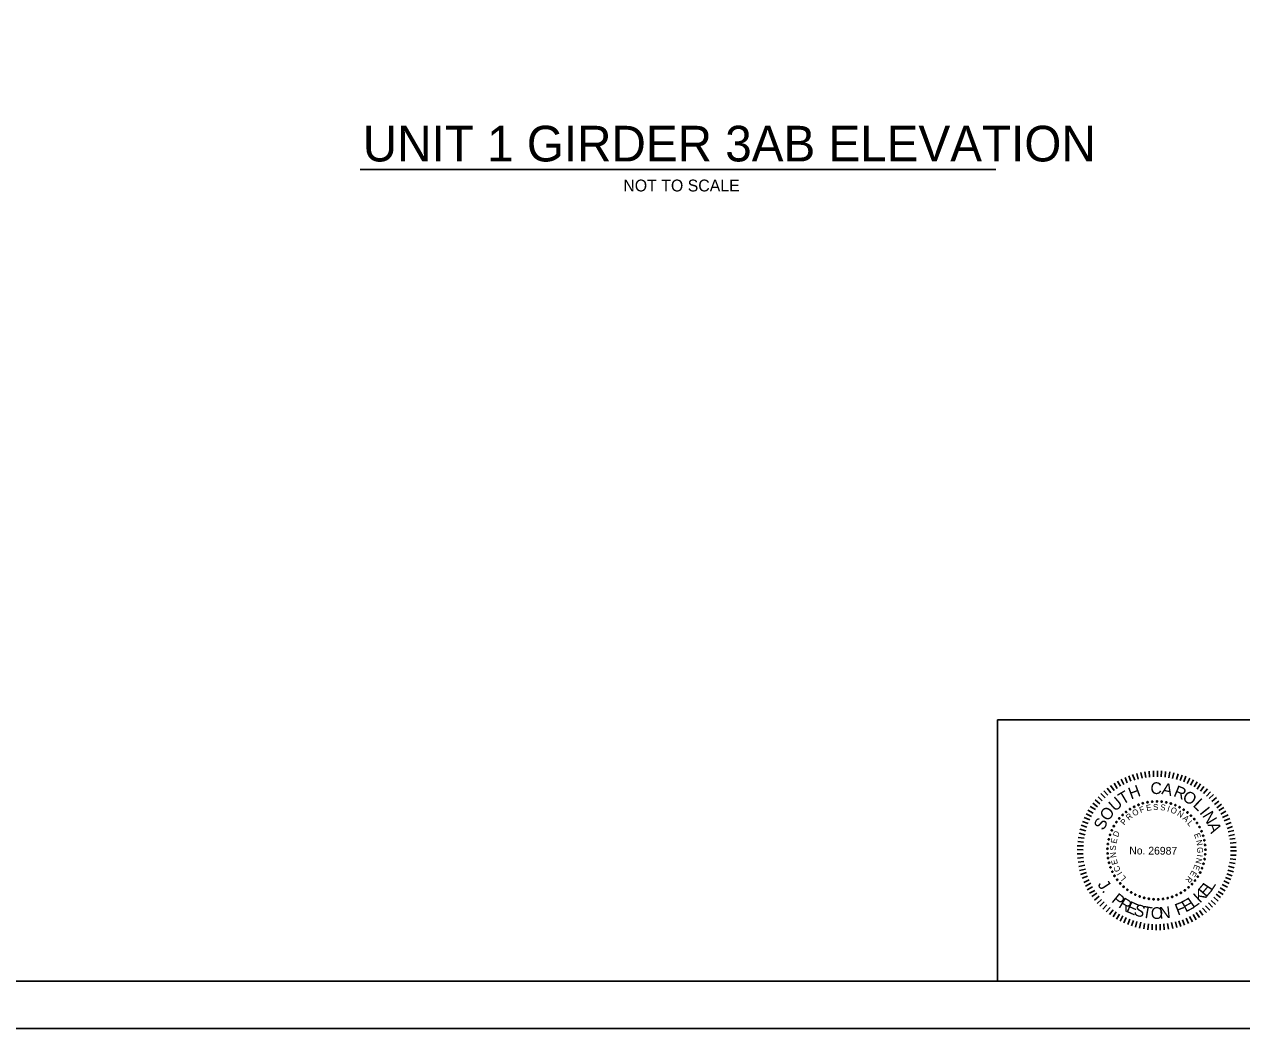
# Model space of a CAD drawing. Extents: x -383 to 7, y -330 to -94.
# Drawn here: x -255.6 to -204.4, y -187.5 to -145.2 of the extents above; entities that cross this region are included whole.
import ezdxf

# ---------------------------------------------------------------- set-up
doc = ezdxf.new("R2010")
doc.units = 0
for name, color, linetype in [('BR_BORDER LINES', 7, 'Continuous'), ('BR_TEXT', 7, 'Continuous'), ('Level 31', 7, 'Continuous')]:
    doc.layers.add(name, color=color, linetype=linetype)

msp = doc.modelspace()

# ---------------------------------------------------------------- linework, layer by layer
at = {"layer": 'BR_BORDER LINES'}
for p, q in [((-214.64, -174.489), (-193.18, -174.489)), ((-214.64, -185.489), (-214.64, -174.489)), ((-297.843, -185.489), (-163.178, -185.489))]:
    msp.add_line(p, q, dxfattribs=at)
at = {"layer": 'BR_TEXT'}
for p, q in [((-241.481, -151.32), (-214.712, -151.32)), ((-209.02, -177.076), (-209.103, -176.842)), ((-208.861, -177.026), (-208.949, -176.795)), ((-208.717, -176.986), (-208.77, -176.742)), ((-208.552, -176.946), (-208.608, -176.709)), ((-208.394, -176.917), (-208.429, -176.673)), ((-208.236, -176.901), (-208.251, -176.657)), ((-208.077, -176.892), (-208.075, -176.634)), ((-207.909, -176.883), (-207.907, -176.636)), ((-207.741, -176.895), (-207.732, -176.637)), ((-207.58, -176.906), (-207.561, -176.663)), ((-207.426, -176.925), (-207.382, -176.681)), ((-207.265, -176.957), (-207.208, -176.721)), ((-207.1, -176.999), (-207.036, -176.756)), ((-206.953, -177.042), (-206.865, -176.813)), ((-206.795, -177.095), (-206.708, -176.862)), ((-209.861, -177.564), (-210.021, -177.363)), ((-209.726, -177.462), (-209.883, -177.258)), ((-209.602, -177.377), (-209.724, -177.16)), ((-209.461, -177.282), (-209.582, -177.065)), ((-209.323, -177.211), (-209.427, -176.987)), ((-209.175, -177.144), (-209.269, -176.92)), ((-206.652, -177.165), (-206.54, -176.942)), ((-206.508, -177.234), (-206.383, -177.012)), ((-206.358, -177.308), (-206.229, -177.093)), ((-206.225, -177.405), (-206.089, -177.19)), ((-206.091, -177.492), (-205.946, -177.291)), ((-205.962, -177.596), (-205.799, -177.398)), ((-210.328, -178.02), (-210.526, -177.864)), ((-210.228, -177.894), (-210.402, -177.724)), ((-210.11, -177.771), (-210.287, -177.594)), ((-209.993, -177.662), (-210.159, -177.482)), ((-205.836, -177.696), (-205.663, -177.519)), ((-205.723, -177.807), (-205.55, -177.634)), ((-205.611, -177.932), (-205.421, -177.765)), ((-205.502, -178.06), (-205.316, -177.907)), ((-210.686, -178.552), (-210.912, -178.441)), ((-210.617, -178.416), (-210.832, -178.287)), ((-210.519, -178.269), (-210.735, -178.137)), ((-210.432, -178.153), (-210.63, -177.993)), ((-205.407, -178.194), (-205.21, -178.038)), ((-205.319, -178.312), (-205.109, -178.183)), ((-205.231, -178.46), (-205.017, -178.335)), ((-210.876, -179.014), (-211.122, -178.923)), ((-210.826, -178.853), (-211.059, -178.766)), ((-210.756, -178.699), (-210.985, -178.598)), ((-205.16, -178.598), (-204.929, -178.49)), ((-205.089, -178.746), (-204.862, -178.648)), ((-205.022, -178.901), (-204.795, -178.817)), ((-210.996, -179.47), (-211.24, -179.437)), ((-210.954, -179.326), (-211.204, -179.262)), ((-210.925, -179.158), (-211.168, -179.098)), ((-204.968, -179.063), (-204.738, -178.976)), ((-204.928, -179.207), (-204.688, -179.151)), ((-204.895, -179.376), (-204.654, -179.316)), ((-211.034, -179.957), (-211.285, -179.955)), ((-211.026, -179.792), (-211.284, -179.79)), ((-211.015, -179.634), (-211.261, -179.605)), ((-204.862, -179.52), (-204.625, -179.491)), ((-204.836, -179.685), (-204.592, -179.66)), ((-204.831, -179.843), (-204.59, -179.845)), ((-211.029, -180.129), (-211.286, -180.133)), ((-211.02, -180.283), (-211.267, -180.312)), ((-211.004, -180.448), (-211.248, -180.484)), ((-204.841, -180.334), (-204.598, -180.367)), ((-204.833, -180.18), (-204.593, -180.189)), ((-204.822, -180.008), (-204.578, -180.01)), ((-210.964, -180.606), (-211.215, -180.659)), ((-210.938, -180.775), (-211.182, -180.831)), ((-210.891, -180.923), (-211.139, -181.006)), ((-204.984, -180.971), (-204.755, -181.059)), ((-204.942, -180.824), (-204.702, -180.885)), ((-204.906, -180.656), (-204.666, -180.713)), ((-204.87, -180.499), (-204.634, -180.538)), ((-210.845, -181.077), (-211.079, -181.161)), ((-210.777, -181.226), (-211.008, -181.334)), ((-210.71, -181.37), (-210.937, -181.489)), ((-205.183, -181.416), (-204.954, -181.538)), ((-205.11, -181.272), (-204.884, -181.384)), ((-205.04, -181.125), (-204.814, -181.213)), ((-210.642, -181.519), (-210.859, -181.644)), ((-210.547, -181.667), (-210.765, -181.792)), ((-210.462, -181.784), (-210.663, -181.93)), ((-210.361, -181.919), (-210.561, -182.075)), ((-205.535, -181.959), (-205.351, -182.118)), ((-205.437, -181.826), (-205.243, -181.975)), ((-205.347, -181.71), (-205.139, -181.839)), ((-205.257, -181.563), (-205.045, -181.692)), ((-210.262, -182.054), (-210.439, -182.217)), ((-210.146, -182.158), (-210.326, -182.338)), ((-210.031, -182.279), (-210.2, -182.463)), ((-209.901, -182.383), (-210.064, -182.57)), ((-209.768, -182.487), (-209.928, -182.678)), ((-206.133, -182.517), (-205.99, -182.71)), ((-206.002, -182.415), (-205.842, -182.605)), ((-205.874, -182.313), (-205.704, -182.5)), ((-205.76, -182.194), (-205.589, -182.377)), ((-205.645, -182.092), (-205.458, -182.258)), ((-209.645, -182.574), (-209.77, -182.782)), ((-209.505, -182.664), (-209.63, -182.879)), ((-209.368, -182.744), (-209.477, -182.967)), ((-209.221, -182.814), (-209.319, -183.037)), ((-209.068, -182.884), (-209.155, -183.11)), ((-208.91, -182.933), (-209.001, -183.166)), ((-208.766, -182.983), (-208.823, -183.219)), ((-208.602, -183.011), (-208.662, -183.258)), ((-207.315, -183.022), (-207.262, -183.27)), ((-207.15, -182.996), (-207.09, -183.233)), ((-207.002, -182.949), (-206.918, -183.183)), ((-206.843, -182.902), (-206.759, -183.13)), ((-206.699, -182.835), (-206.591, -183.059)), ((-206.554, -182.768), (-206.432, -182.992)), ((-206.402, -182.69), (-206.277, -182.907)), ((-206.268, -182.602), (-206.135, -182.812)), ((-208.444, -183.057), (-208.484, -183.29)), ((-208.287, -183.076), (-208.306, -183.323)), ((-208.129, -183.087), (-208.131, -183.335)), ((-207.961, -183.099), (-207.963, -183.343)), ((-207.792, -183.09), (-207.787, -183.338)), ((-207.631, -183.081), (-207.616, -183.329)), ((-207.476, -183.065), (-207.437, -183.299))]:
    msp.add_line(p, q, dxfattribs=at)
for centre, start, end in [((-208.126, -177.93), 5.0653, 185.0653), ((-208.126, -177.93), 185.0653, 5.0653), ((-207.926, -177.923), 359.5268, 179.5268), ((-207.926, -177.923), 179.5268, 359.5268), ((-207.727, -177.934), 353.9884, 173.9884), ((-209.223, -178.364), 38.2961, 218.2961), ((-209.223, -178.364), 218.2961, 38.2961), ((-209.06, -178.248), 32.7576, 212.7576), ((-209.06, -178.248), 212.7576, 32.7576), ((-208.887, -178.149), 27.2191, 207.2191), ((-208.887, -178.149), 207.2191, 27.2191), ((-208.706, -178.067), 21.6807, 201.6807), ((-208.706, -178.067), 201.6807, 21.6807), ((-208.517, -178.003), 16.1422, 196.1422), ((-208.517, -178.003), 196.1422, 16.1422), ((-208.323, -177.957), 10.6038, 190.6038), ((-208.323, -177.957), 190.6038, 10.6038), ((-207.727, -177.934), 173.9884, 353.9884), ((-207.531, -177.965), 168.4499, 348.4499), ((-207.531, -177.965), 348.4499, 168.4499), ((-207.338, -178.015), 162.9114, 342.9114), ((-207.338, -178.015), 342.9114, 162.9114), ((-207.15, -178.083), 157.373, 337.373), ((-207.15, -178.083), 337.373, 157.373), ((-206.97, -178.169), 151.8345, 331.8345), ((-206.97, -178.169), 331.8345, 151.8345), ((-206.8, -178.272), 146.2961, 326.2961), ((-206.8, -178.272), 326.2961, 146.2961), ((-206.639, -178.39), 140.7576, 320.7576), ((-206.639, -178.39), 320.7576, 140.7576), ((-209.74, -178.964), 60.4499, 240.4499), ((-209.74, -178.964), 240.4499, 60.4499), ((-209.633, -178.796), 54.9114, 234.9114), ((-209.633, -178.796), 234.9114, 54.9114), ((-209.511, -178.639), 49.373, 229.373), ((-209.511, -178.639), 229.373, 49.373), ((-209.373, -178.495), 43.8345, 223.8345), ((-209.373, -178.495), 223.8345, 43.8345), ((-206.492, -178.524), 135.2191, 315.2191), ((-206.492, -178.524), 315.2191, 135.2191), ((-206.357, -178.671), 129.6807, 309.6807), ((-206.357, -178.671), 309.6807, 129.6807), ((-206.238, -178.831), 124.1422, 304.1422), ((-206.238, -178.831), 304.1422, 124.1422), ((-209.903, -179.328), 71.5268, 251.5268), ((-209.903, -179.328), 251.5268, 71.5268), ((-209.83, -179.142), 65.9884, 245.9884), ((-209.83, -179.142), 245.9884, 65.9884), ((-206.135, -179.001), 118.6038, 298.6038), ((-206.135, -179.001), 298.6038, 118.6038), ((-206.048, -179.181), 113.0653, 293.0653), ((-206.048, -179.181), 293.0653, 113.0653), ((-205.979, -179.368), 107.5268, 287.5268), ((-205.979, -179.368), 287.5268, 107.5268), ((-210.009, -179.914), 88.1422, 268.1422), ((-209.993, -179.716), 82.6038, 262.6038), ((-210.009, -179.914), 268.1422, 88.1422), ((-209.993, -179.716), 262.6038, 82.6038), ((-209.957, -179.52), 77.0653, 257.0653), ((-209.957, -179.52), 257.0653, 77.0653), ((-205.929, -179.561), 101.9884, 281.9884), ((-205.929, -179.561), 281.9884, 101.9884), ((-205.897, -179.758), 96.4499, 276.4499), ((-205.885, -179.957), 90.9114, 270.9114), ((-205.897, -179.758), 276.4499, 96.4499), ((-205.885, -179.957), 270.9114, 90.9114), ((-210.006, -180.114), 93.6807, 273.6807), ((-209.984, -180.312), 99.2191, 279.2191), ((-210.006, -180.114), 273.6807, 93.6807), ((-209.984, -180.312), 279.2191, 99.2191), ((-209.943, -180.507), 104.7576, 284.7576), ((-209.943, -180.507), 284.7576, 104.7576), ((-205.918, -180.353), 79.8345, 259.8345), ((-205.918, -180.353), 259.8345, 79.8345), ((-205.892, -180.156), 85.373, 265.373), ((-205.892, -180.156), 265.373, 85.373), ((-209.884, -180.697), 110.2961, 290.2961), ((-209.884, -180.697), 290.2961, 110.2961), ((-209.806, -180.881), 115.8345, 295.8345), ((-209.806, -180.881), 295.8345, 115.8345), ((-206.108, -180.918), 63.2191, 243.2191), ((-206.108, -180.918), 243.2191, 63.2191), ((-206.026, -180.737), 68.7576, 248.7576), ((-206.026, -180.737), 248.7576, 68.7576), ((-205.963, -180.548), 74.2961, 254.2961), ((-205.963, -180.548), 254.2961, 74.2961), ((-209.711, -181.056), 121.373, 301.373), ((-209.711, -181.056), 301.373, 121.373), ((-209.599, -181.221), 126.9114, 306.9114), ((-209.599, -181.221), 306.9114, 126.9114), ((-209.472, -181.375), 132.4499, 312.4499), ((-209.472, -181.375), 312.4499, 132.4499), ((-209.331, -181.515), 137.9884, 317.9884), ((-209.331, -181.515), 317.9884, 137.9884), ((-206.596, -181.543), 41.0653, 221.0653), ((-206.452, -181.406), 46.6038, 226.6038), ((-206.452, -181.406), 226.6038, 46.6038), ((-206.321, -181.255), 52.1422, 232.1422), ((-206.321, -181.255), 232.1422, 52.1422), ((-206.207, -181.092), 57.6807, 237.6807), ((-206.207, -181.092), 237.6807, 57.6807), ((-209.177, -181.642), 143.5268, 323.5268), ((-209.177, -181.642), 323.5268, 143.5268), ((-209.011, -181.753), 149.0653, 329.0653), ((-209.011, -181.753), 329.0653, 149.0653), ((-208.836, -181.847), 154.6038, 334.6038), ((-208.836, -181.847), 334.6038, 154.6038), ((-208.652, -181.924), 160.1422, 340.1422), ((-208.652, -181.924), 340.1422, 160.1422), ((-208.462, -181.983), 165.6807, 345.6807), ((-208.462, -181.983), 345.6807, 165.6807), ((-208.267, -182.023), 171.2191, 351.2191), ((-208.267, -182.023), 351.2191, 171.2191), ((-208.068, -182.045), 356.7576, 176.7576), ((-207.869, -182.047), 2.2961, 182.2961), ((-207.67, -182.029), 7.8345, 187.8345), ((-207.67, -182.029), 187.8345, 7.8345), ((-207.474, -181.993), 13.373, 193.373), ((-207.474, -181.993), 193.373, 13.373), ((-207.283, -181.938), 18.9114, 198.9114), ((-207.283, -181.938), 198.9114, 18.9114), ((-207.098, -181.865), 24.4499, 204.4499), ((-207.098, -181.865), 204.4499, 24.4499), ((-206.92, -181.774), 29.9884, 209.9884), ((-206.92, -181.774), 209.9884, 29.9884), ((-206.752, -181.667), 35.5268, 215.5268), ((-206.752, -181.667), 215.5268, 35.5268), ((-206.596, -181.543), 221.0653, 41.0653), ((-208.068, -182.045), 176.7576, 356.7576), ((-207.869, -182.047), 182.2961, 2.2961)]:
    msp.add_arc(centre, 0.028, start, end, dxfattribs=at)
at = {"layer": 'Level 31'}
msp.add_lwpolyline([(-305.176, -187.489), (-161.176, -187.489), (-161.176, -99.489), (-305.176, -99.489)], close=True, dxfattribs=at)

# ---------------------------------------------------------------- texts
at = {"layer": 'BR_TEXT'}
for s, height, p in [('UNIT 1 GIRDER 3AB ELEVATION', 1.5, (-241.378, -150.983)), ('NOT TO SCALE', 0.5, (-230.403, -152.247))]:
    msp.add_text(s, height=height, dxfattribs=at).set_placement(p)
for s, height, rotation, p in [('H', 0.496, 20.3637, (-209.018, -177.846)), ('C', 0.496, 359.5482, (-208.2, -177.612)), ('A', 0.496, 348.1981, (-207.755, -177.609)), ('R', 0.496, 337.4344, (-207.262, -177.689)), ('U', 0.496, 40.8022, (-209.694, -178.375)), ('T', 0.496, 30.4992, (-209.37, -178.076)), ('O', 0.496, 326.5869, (-206.893, -177.836)), ('L', 0.496, 315.9488, (-206.442, -178.107)), ('O', 0.496, 52.0267, (-209.993, -178.79)), ('R', 0.249, 40.3949, (-209.107, -178.737)), ('O', 0.249, 30.8477, (-208.882, -178.561)), ('F', 0.249, 20.6127, (-208.613, -178.417)), ('E', 0.249, 11.4103, (-208.352, -178.33)), ('S', 0.249, 2.208, (-208.081, -178.286)), ('S', 0.249, 352.6608, (-207.796, -178.287)), ('I', 0.249, 343.1136, (-207.515, -178.335)), ('O', 0.249, 338.4392, (-207.381, -178.376)), ('N', 0.249, 328.2042, (-207.103, -178.501)), ('I', 0.496, 308.6613, (-206.157, -178.404)), ('N', 0.496, 300.7037, (-206.035, -178.521)), ('S', 0.496, 63.2511, (-210.174, -179.173)), ('P', 0.249, 49.9421, (-209.299, -178.947)), ('A', 0.249, 318.657, (-206.867, -178.662)), ('L', 0.249, 309.4546, (-206.668, -178.851)), ('A', 0.496, 289.4792, (-205.798, -178.894)), ('D', 0.249, 69.0364, (-209.567, -179.448)), ('E', 0.249, 291.049, (-206.372, -179.312)), ('S', 0.249, 87.786, (-209.656, -179.999)), ('E', 0.249, 78.2388, (-209.633, -179.715)), ('No. 26987', 0.327, 359.5268, (-209.092, -180.153)), ('N', 0.249, 281.8466, (-206.283, -179.572)), ('G', 0.249, 272.2995, (-206.237, -179.853)), ('N', 0.249, 97.3332, (-209.632, -180.283)), ('E', 0.249, 106.5355, (-209.564, -180.549)), ('N', 0.249, 257.7339, (-206.256, -180.287)), ('I', 0.249, 262.4084, (-206.238, -180.149)), ('C', 0.249, 116.4266, (-209.444, -180.819)), ('I', 0.249, 121.1011, (-209.372, -180.939)), ('E', 0.249, 238.9844, (-206.44, -180.814)), ('E', 0.249, 248.1867, (-206.328, -180.563)), ('J', 0.494, 302.9559, (-210.441, -181.421)), ('L', 0.249, 129.9595, (-209.209, -181.147)), ('R', 0.249, 229.782, (-206.591, -181.044)), ('E', 0.494, 49.3639, (-205.857, -181.989)), ('L', 0.494, 56.4247, (-205.627, -181.718)), ('.', 0.494, 309.3974, (-210.264, -181.693)), ('P', 0.494, 321.1035, (-209.871, -182.13)), ('R', 0.494, 328.5359, (-209.578, -182.362)), ('E', 0.494, 28.1814, (-206.719, -182.605)), ('L', 0.494, 35.2422, (-206.407, -182.436)), ('K', 0.494, 42.3031, (-206.118, -182.229)), ('E', 0.494, 335.9684, (-209.257, -182.555)), ('S', 0.494, 343.0292, (-208.932, -182.698)), ('T', 0.494, 350.4617, (-208.573, -182.804)), ('O', 0.494, 358.1419, (-208.192, -182.863)), ('N', 0.494, 5.8221, (-207.805, -182.872)), ('F', 0.494, 21.1206, (-207.05, -182.735))]:
    msp.add_text(s, height=height, rotation=rotation, dxfattribs=at).set_placement(p)

doc.saveas('drawing.dxf')
